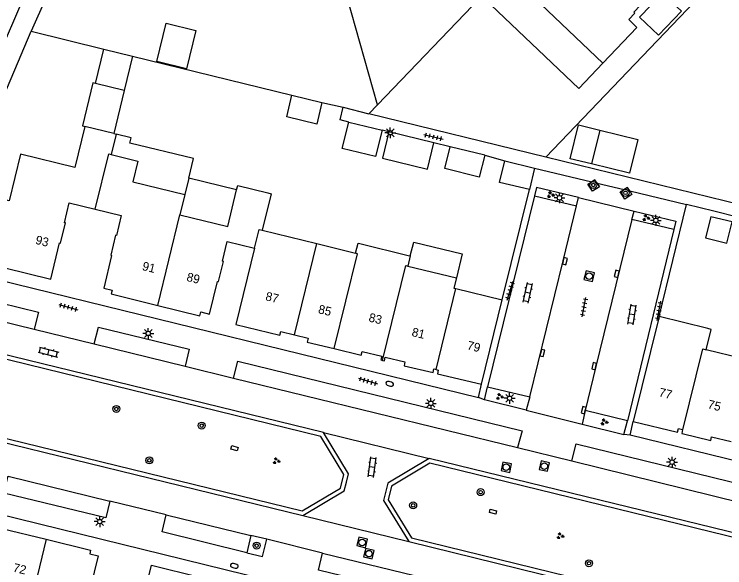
# Model space of a CAD drawing. Extents: x 125000 to 129004, y 397500 to 399008.
# Drawn here: x 126436.9 to 126518.3, y 398005.2 to 398068.5 of the extents above; entities that cross this region are included whole.
import ezdxf

# ---------------------------------------------------------------- set-up
doc = ezdxf.new("R2010")
doc.units = 0
for name, color, linetype in [('gg-afsc-erfafscheiding', 7, 'Continuous'), ('gg-afsc-hekwerk', 7, 'Continuous'), ('gg-anno-huisnummerreeks BGT', 7, 'Continuous'), ('gg-bbg-bijgebouw', 7, 'Continuous'), ('gg-bbg-gedigitaliseerde bijgebouw', 7, 'Continuous'), ('gg-bbg-hoofdgebouw', 7, 'Continuous'), ('gg-bbg-luifel en loopbrug', 7, 'Continuous'), ('gg-bbg-tussenscheiding', 7, 'Continuous'), ('gg-knt-verharding', 7, 'Continuous'), ('gg-knt-verharding nz', 7, 'Continuous'), ('gt-grn-groengrens', 7, 'Continuous'), ('gt-grn-vlakafsluiter', 7, 'Continuous'), ('gt-grn-weggrens', 7, 'Continuous'), ('gt-symb-boom', 7, 'Continuous'), ('gt-symb-brandkraan', 7, 'Continuous'), ('gt-symb-groenvak', 7, 'Continuous'), ('gt-symb-klinker verharding', 7, 'Continuous'), ('gt-symb-kolk', 7, 'Continuous'), ('gt-symb-kolk center center', 7, 'Continuous'), ('gt-symb-lichtmast', 7, 'Continuous'), ('gt-symb-rioolschacht', 7, 'Continuous'), ('gt-symb-tegel verharding', 7, 'Continuous')]:
    doc.layers.add(name, color=color, linetype=linetype)

# ---------------------------------------------------------------- blocks, each defined once
blk = doc.blocks.new('gt0-GRVAK')
at = {"layer": 'gt-symb-groenvak'}
for p, q in [((-0.11, 0.189), (-0.228, 0.24)), ((-0.182, 0.153), (0.088, 0.153)), ((-0.091, 0.211), (-0.156, 0.322)), ((-0.047, 0.214), (-0.047, 0.393)), ((-0.004, 0.211), (0.061, 0.322)), ((0.015, 0.189), (0.133, 0.24)), ((0.262, -0.052), (0.197, 0.059)), ((0.305, -0.049), (0.305, 0.13)), ((0.349, -0.052), (0.414, 0.059)), ((-0.245, -0.228), (-0.363, -0.177)), ((-0.318, -0.264), (-0.047, -0.264)), ((-0.226, -0.206), (-0.291, -0.095)), ((-0.183, -0.203), (-0.183, -0.024)), ((-0.139, -0.206), (-0.074, -0.095)), ((-0.12, -0.228), (-0.002, -0.177)), ((0.243, -0.074), (0.125, -0.023)), ((0.17, -0.11), (0.441, -0.11)), ((0.368, -0.074), (0.486, -0.023))]:
    blk.add_line(p, q, dxfattribs=at)
blk = doc.blocks.new('gt0-BOOM')
at = {"layer": 'gt-symb-boom'}
for radius in [0.4, 0.2]:
    blk.add_circle((0, 0), radius, dxfattribs=at)
blk = doc.blocks.new('gt0-TEG1')
at = {"layer": 'gt-symb-tegel verharding'}
for p, q in [((-1.125, 0), (1.125, 0)), ((-0.9, -0.25), (-0.9, 0.25)), ((-0.45, -0.25), (-0.45, 0.25)), ((0, -0.25), (0, 0.25)), ((0.45, -0.25), (0.45, 0.25)), ((0.9, -0.25), (0.9, 0.25))]:
    blk.add_line(p, q, dxfattribs=at)
blk = doc.blocks.new('gt0-LMAST')
at = {"layer": 'gt-symb-lichtmast'}
for p, q in [((-0.182, 0.173), (-0.447, 0.438)), ((-0.005, 0.246), (-0.005, 0.621)), ((0.172, 0.173), (0.437, 0.438)), ((-0.255, -0.004), (-0.63, -0.004)), ((-0.182, -0.181), (-0.447, -0.446)), ((-0.005, -0.254), (-0.005, -0.629)), ((0.437, -0.446), (0.172, -0.181)), ((0.245, -0.004), (0.62, -0.004))]:
    blk.add_line(p, q, dxfattribs=at)
blk.add_circle((-0.005, -0.004), 0.25, dxfattribs=at)
blk = doc.blocks.new('gt0-KOLK')
at = {"layer": 'gt-symb-kolk'}
blk.add_lwpolyline([(0, 0), (0.375, 0), (0.375, 0.4), (-0.375, 0.4), (-0.375, 0), (0, 0)], dxfattribs=at)
blk = doc.blocks.new('gt0-KL1')
at = {"layer": 'gt-symb-klinker verharding'}
for p, q in [((-1.15, 0.3), (1.15, 0.3)), ((-1, -0.3), (-1, 0.3)), ((-0.5, 0.3), (-0.5, 0.45)), ((0, -0.3), (0, 0.3)), ((0.5, 0.3), (0.5, 0.45)), ((1, -0.3), (1, 0.3)), ((-1.15, -0.3), (1.15, -0.3)), ((-0.5, -0.45), (-0.5, -0.3)), ((0.5, -0.45), (0.5, -0.3))]:
    blk.add_line(p, q, dxfattribs=at)
blk = doc.blocks.new('gt0-RS')
at = {"layer": 'gt-symb-rioolschacht'}
blk.add_lwpolyline([(-0.5, -0.5), (0.5, -0.5), (0.5, 0.5), (-0.5, 0.5)], close=True, dxfattribs=at)
blk.add_circle((0, 0), 0.375, dxfattribs=at)
blk = doc.blocks.new('gt0-KOLKCC')
at = {"layer": 'gt-symb-kolk center center'}
blk.add_lwpolyline([(-0.375, 0.2), (0.375, 0.2), (0.375, -0.2), (-0.375, -0.2)], close=True, dxfattribs=at)
blk = doc.blocks.new('gt0-BR')
at = {"layer": 'gt-symb-brandkraan'}
for centre, radius, start, end in [((-0.244, 0), 0.206, 107.56694, 252.43307), ((0.599, -2.664), 3, 106.89205, 107.56694), ((0, -0.691), 0.938, 73.10799, 106.89205), ((-0.599, -2.664), 3, 72.43309, 73.10799), ((0.244, 0), 0.206, 287.56695, 72.43309), ((0.599, 2.664), 3, 252.43307, 253.10797), ((0, 0.691), 0.938, 253.10797, 286.89206), ((-0.599, 2.664), 3, 286.89206, 287.56695)]:
    blk.add_arc(centre, radius, start, end, dxfattribs=at)

msp = doc.modelspace()

# ---------------------------------------------------------------- linework, layer by layer
at = {"layer": 'gg-afsc-erfafscheiding'}
for p, q in [((126497.759, 398052.161), (126477.496, 398057.12)), ((126479.812, 398055.034), (126479.032, 398055.222)), ((126486.811, 398053.349), (126484.965, 398053.793)), ((126490.772, 398052.372), (126493.061, 398051.732)), ((126517.01, 398045.958), (126513.88, 398046.725)), ((126519.718, 398045.294), (126517.01, 398045.958))]:
    msp.add_line(p, q, dxfattribs=at)
msp.add_lwpolyline([(126475.221, 398056.16), (126474.219, 398056.415), (126474.564, 398057.864)], dxfattribs=at)
at = {"layer": 'gg-afsc-hekwerk'}
for p, q in [((126446.666, 398084.323), (126438.871, 398066.562)), ((126499.871, 398080.447), (126478.524, 398058.123)), ((126478.524, 398058.123), (126474.789, 398071.279)), ((126497.781, 398052.156), (126514.794, 398069.932)), ((126432.376, 398051.273), (126438.871, 398066.562)), ((126477.496, 398057.12), (126478.524, 398058.123)), ((126474.564, 398057.864), (126477.496, 398057.12)), ((126497.781, 398052.156), (126497.759, 398052.161)), ((126558.695, 398037.234), (126497.781, 398052.156)), ((126492.786, 398035.816), (126495.918, 398048.44)), ((126510.759, 398033.93), (126513.88, 398046.725))]:
    msp.add_line(p, q, dxfattribs=at)
at = {"layer": 'gg-bbg-bijgebouw'}
for p, q in [((126446.231, 398060.585), (126447.182, 398064.497)), ((126447.182, 398064.497), (126450.45, 398063.704)), ((126450.45, 398063.704), (126449.506, 398059.794)), ((126449.506, 398059.794), (126446.231, 398060.585)), ((126468.714, 398059.241), (126472.147, 398058.406)), ((126475.221, 398056.16), (126479.032, 398055.222)), ((126490.772, 398052.372), (126486.811, 398053.349)), ((126493.061, 398051.732), (126496.484, 398050.89)), ((126496.484, 398050.89), (126495.918, 398048.44))]:
    msp.add_line(p, q, dxfattribs=at)
for points in [[(126472.147, 398058.406), (126471.568, 398055.943), (126468.122, 398056.753), (126468.714, 398059.241)], [(126479.032, 398055.222), (126478.291, 398052.212), (126474.48, 398053.15), (126475.221, 398056.16)], [(126490.772, 398052.372), (126490.154, 398049.867), (126486.209, 398050.847), (126486.811, 398053.349)], [(126495.918, 398048.44), (126492.469, 398049.238), (126493.061, 398051.732)]]:
    msp.add_lwpolyline(points, dxfattribs=at)
at = {"layer": 'gg-bbg-gedigitaliseerde bijgebouw'}
for p, q in [((126484.965, 398053.793), (126479.812, 398055.034)), ((126503.936, 398055.254), (126502.988, 398051.368))]:
    msp.add_line(p, q, dxfattribs=at)
for points in [[(126457.711, 398066.63), (126456.637, 398062.259), (126453.238, 398063.094), (126454.311, 398067.464), (126457.711, 398066.63)], [(126502.988, 398051.368), (126500.559, 398051.961), (126501.508, 398055.847), (126503.936, 398055.254)], [(126479.812, 398055.034), (126479.076, 398052.02), (126484.225, 398050.763), (126484.965, 398053.793)], [(126518.484, 398042.309), (126519.079, 398044.737), (126516.651, 398045.332), (126516.056, 398042.904), (126518.484, 398042.309)]]:
    msp.add_lwpolyline(points, dxfattribs=at)
at = {"layer": 'gg-bbg-hoofdgebouw'}
for p, q in [((126493.466, 398073.236), (126504.297, 398062.887)), ((126448.324, 398054.841), (126445.011, 398055.657)), ((126448.596, 398054.774), (126448.025, 398052.453)), ((126448.324, 398054.841), (126448.596, 398054.774)), ((126465.303, 398043.801), (126471.549, 398042.257)), ((126471.549, 398042.257), (126476.002, 398041.156)), ((126476.491, 398042.273), (126482.021, 398040.912)), ((126482.26, 398040.853), (126481.973, 398039.688)), ((126482.021, 398040.912), (126482.26, 398040.853)), ((126481.973, 398039.688), (126487.529, 398038.328)), ((126487.466, 398037.109), (126492.786, 398035.816)), ((126490.423, 398026.165), (126492.786, 398035.816)), ((126510.759, 398033.93), (126507.769, 398021.909)), ((126516.298, 398032.549), (126510.759, 398033.93)), ((126521.226, 398028.872), (126516.117, 398030.121))]:
    msp.add_line(p, q, dxfattribs=at)
for points in [[(126504.297, 398062.887), (126508.189, 398067.001), (126507.264, 398067.898), (126507.943, 398068.621), (126507.834, 398068.722), (126512.297, 398073.455), (126507.899, 398077.667), (126506.612, 398076.318), (126504.128, 398078.665), (126501.88, 398076.264), (126501.591, 398076.535), (126499.813, 398074.691), (126497.232, 398077.178), (126493.466, 398073.236)], [(126445.011, 398055.657), (126443.864, 398050.974), (126437.638, 398052.497), (126436.34, 398047.159), (126435.32, 398047.408), (126434.335, 398043.384), (126435.343, 398043.136), (126434.641, 398040.221), (126435.975, 398039.898), (126435.871, 398039.471), (126441.108, 398038.201), (126442.119, 398042.343), (126442.226, 398042.317), (126442.791, 398044.63), (126442.684, 398044.656), (126443.235, 398046.911), (126446.211, 398046.185)], [(126448.025, 398052.453), (126451.094, 398051.681), (126450.506, 398049.344), (126456.443, 398047.895)], [(126455.899, 398045.553), (126461.362, 398044.219), (126462.386, 398048.415)], [(126462.386, 398048.415), (126462.505, 398048.901), (126465.962, 398048.057)], [(126456.443, 398047.895), (126455.873, 398045.559), (126455.899, 398045.553)], [(126465.962, 398048.057), (126466.33, 398047.967), (126465.303, 398043.801)], [(126446.211, 398046.185), (126449.187, 398045.458), (126448.636, 398043.203), (126448.53, 398043.229), (126447.969, 398040.922), (126448.076, 398040.896), (126447.167, 398037.17), (126448.137, 398036.927), (126448.032, 398036.5), (126453.369, 398035.188)], [(126453.369, 398035.188), (126458.183, 398034.01), (126458.288, 398034.438), (126459.259, 398034.2), (126460.195, 398037.937), (126460.302, 398037.91), (126460.87, 398040.232), (126460.763, 398040.258), (126461.314, 398042.512), (126464.423, 398041.751)], [(126476.002, 398041.156), (126476.29, 398042.323), (126476.491, 398042.273)], [(126464.423, 398041.751), (126462.284, 398033.009), (126467.328, 398031.775), (126467.432, 398032.203), (126469.001, 398031.817)], [(126487.529, 398038.328), (126487.244, 398037.163), (126487.466, 398037.109)], [(126516.117, 398030.121), (126516.698, 398032.449), (126516.298, 398032.549)], [(126469.001, 398031.817), (126470.569, 398031.431), (126470.465, 398031.004), (126473.556, 398030.251)], [(126473.556, 398030.251), (126476.647, 398029.497), (126476.755, 398029.937), (126478.994, 398029.385), (126478.888, 398028.955), (126479.089, 398028.904)], [(126479.089, 398028.904), (126479.29, 398028.852), (126479.399, 398029.278), (126481.651, 398028.725), (126481.547, 398028.297), (126484.858, 398027.498), (126484.96, 398027.919), (126485.208, 398027.86)], [(126485.208, 398027.86), (126485.456, 398027.801), (126485.354, 398027.373), (126490.423, 398026.165)], [(126507.769, 398021.909), (126512.833, 398020.673), (126512.938, 398021.1), (126513.423, 398020.982)], [(126513.423, 398020.982), (126513.326, 398020.553), (126513.356, 398020.546)], [(126513.356, 398020.546), (126516.638, 398019.737), (126516.744, 398020.164), (126518.981, 398019.614)], [(126429.466, 398001.931), (126432.435, 398001.214), (126432.98, 398003.468), (126432.873, 398003.493), (126433.43, 398005.796), (126433.536, 398005.77), (126434.434, 398009.484), (126435.413, 398009.248), (126435.517, 398009.675), (126440.596, 398008.435)], [(126440.596, 398008.435), (126445.675, 398007.194), (126445.57, 398006.766), (126446.544, 398006.527), (126445.629, 398002.789), (126445.736, 398002.763), (126445.166, 398000.437), (126445.059, 398000.463), (126444.506, 397998.204), (126447.495, 397997.472)], [(126447.495, 397997.472), (126450.483, 397996.741), (126451.036, 397999), (126450.929, 397999.026), (126451.496, 398001.343), (126451.603, 398001.317), (126452.623, 398005.483), (126458.183, 398004.12)]]:
    msp.add_lwpolyline(points, dxfattribs=at)
at = {"layer": 'gg-bbg-luifel en loopbrug'}
for p, q in [((126449.506, 398059.794), (126448.324, 398054.841)), ((126456.897, 398049.755), (126456.443, 398047.895)), ((126462.386, 398048.415), (126456.897, 398049.755))]:
    msp.add_line(p, q, dxfattribs=at)
for points in [[(126493.466, 398073.236), (126490.703, 398070.344), (126501.534, 398059.995), (126504.297, 398062.887)], [(126508.5, 398068.165), (126511.125, 398070.912), (126513.294, 398068.84), (126510.669, 398066.092), (126508.5, 398068.165)], [(126446.231, 398060.585), (126445.94, 398060.657), (126444.726, 398055.727), (126445.011, 398055.657)], [(126456.897, 398049.755), (126457.443, 398051.99), (126450.157, 398053.768), (126450.301, 398054.358), (126448.596, 398054.774)], [(126503.936, 398055.254), (126508.308, 398054.187), (126507.36, 398050.302), (126502.988, 398051.368)], [(126482.26, 398040.853), (126482.651, 398042.441), (126488.205, 398041.074), (126487.529, 398038.328)]]:
    msp.add_lwpolyline(points, dxfattribs=at)
at = {"layer": 'gg-bbg-tussenscheiding'}
for p, q in [((126453.369, 398035.188), (126455.899, 398045.553)), ((126469.001, 398031.817), (126471.549, 398042.257)), ((126485.208, 398027.86), (126487.466, 398037.109))]:
    msp.add_line(p, q, dxfattribs=at)
for points in [[(126446.211, 398046.185), (126447.757, 398052.52), (126448.025, 398052.453)], [(126464.423, 398041.751), (126464.945, 398043.89), (126465.303, 398043.801)], [(126473.556, 398030.251), (126476.206, 398041.106), (126476.002, 398041.156)], [(126479.089, 398028.904), (126481.736, 398039.746), (126481.973, 398039.688)], [(126513.423, 398020.982), (126513.461, 398020.973), (126515.726, 398030.217), (126516.117, 398030.121)], [(126440.596, 398008.435), (126437.808, 397996.896), (126438.016, 397996.845)]]:
    msp.add_lwpolyline(points, dxfattribs=at)
at = {"layer": 'gg-knt-verharding'}
for p, q in [((126496.459, 398047.735), (126491.103, 398025.877)), ((126496.459, 398047.735), (126501.279, 398046.577)), ((126501.279, 398046.577), (126501.501, 398047.536)), ((126507.615, 398045.03), (126507.861, 398045.984)), ((126512.419, 398043.862), (126507.615, 398045.03)), ((126512.419, 398043.862), (126507.098, 398021.996)), ((126427.531, 398039.968), (126490.06, 398024.642)), ((126472.323, 398020.648), (126421.117, 398033.16)), ((126439.2, 398032.462), (126446.064, 398030.791)), ((126456.479, 398028.241), (126462.023, 398026.864)), ((126490.06, 398024.642), (126490.423, 398026.165)), ((126490.765, 398024.379), (126491.103, 398025.877)), ((126491.103, 398025.877), (126495.932, 398024.715)), ((126495.932, 398024.715), (126495.521, 398023.199)), ((126495.521, 398023.199), (126490.765, 398024.379)), ((126418.425, 398023.739), (126469.973, 398011.151)), ((126502.289, 398023.161), (126501.93, 398021.611)), ((126507.098, 398021.996), (126502.289, 398023.161)), ((126501.93, 398021.611), (126506.714, 398020.433)), ((126506.714, 398020.433), (126507.098, 398021.996)), ((126507.432, 398020.343), (126507.769, 398021.909)), ((126474.648, 398015.856), (126472.003, 398020.211)), ((126684.578, 397977.097), (126507.432, 398020.343)), ((126494.535, 398018.934), (126500.727, 398017.394)), ((126680.269, 397969.791), (126484.428, 398017.669)), ((126682.484, 397968.735), (126484.508, 398017.135)), ((126417.28, 398015.702), (126579.422, 397976.046)), ((126454.327, 398011.228), (126447.887, 398012.785)), ((126464.007, 398008.877), (126463.533, 398006.895)), ((126465.828, 398008.433), (126464.007, 398008.877)), ((126472.224, 398006.846), (126465.828, 398008.433)), ((126482.394, 398008.606), (126680.419, 397960.251)), ((126482.075, 398008.169), (126677.934, 397960.343))]:
    msp.add_line(p, q, dxfattribs=at)
for points in [[(126503.64, 398049.177), (126503.927, 398048.739), (126503.121, 398048.246), (126502.586, 398049.062), (126503.017, 398049.326)], [(126503.64, 398049.177), (126503.392, 398049.555), (126503.017, 398049.326)], [(126501.501, 398047.536), (126496.699, 398048.671), (126496.459, 398047.735)], [(126507.365, 398048.285), (126507.63, 398047.866), (126506.803, 398047.36), (126506.29, 398048.171), (126506.725, 398048.438)], [(126507.365, 398048.285), (126507.117, 398048.678), (126506.725, 398048.438)], [(126495.932, 398024.715), (126499.756, 398040.293), (126501.279, 398046.577)], [(126507.861, 398045.984), (126512.666, 398044.818), (126512.419, 398043.862)], [(126507.615, 398045.03), (126503.494, 398028.192), (126502.289, 398023.161)], [(126426.623, 398037.628), (126439.718, 398034.413), (126439.2, 398032.462)], [(126472.003, 398020.211), (126420.621, 398032.767), (126420.736, 398033.238)], [(126446.064, 398030.791), (126446.565, 398032.719), (126456.941, 398030.187), (126456.479, 398028.241)], [(126462.023, 398026.864), (126462.518, 398028.826), (126495.052, 398020.853), (126494.535, 398018.934)], [(126418.425, 398023.739), (126418.544, 398024.225), (126469.892, 398011.685)], [(126474.939, 398014.955), (126475.183, 398015.937), (126472.323, 398020.648)], [(126500.727, 398017.394), (126501.227, 398019.359), (126555.856, 398005.956), (126555.377, 398004)], [(126484.428, 398017.669), (126479.676, 398014.842), (126479.205, 398012.858), (126482.075, 398008.169)], [(126484.508, 398017.135), (126480.114, 398014.521), (126479.739, 398012.943), (126482.394, 398008.606)], [(126469.892, 398011.685), (126474.26, 398014.295), (126474.648, 398015.856)], [(126447.887, 398012.785), (126447.42, 398010.899), (126435.726, 398013.704), (126436.225, 398015.67)], [(126469.973, 398011.151), (126474.695, 398013.973), (126474.939, 398014.955)], [(126463.533, 398006.895), (126453.846, 398009.275), (126454.327, 398011.228)], [(126463.533, 398006.895), (126465.339, 398006.457), (126465.828, 398008.433)], [(126484.004, 398003.971), (126483.533, 398002.031), (126471.736, 398004.912), (126472.224, 398006.846)]]:
    msp.add_lwpolyline(points, dxfattribs=at)
at = {"layer": 'gg-knt-verharding nz'}
for p, q in [((126426.123, 398035.643), (126439.2, 398032.462)), ((126446.064, 398030.791), (126456.479, 398028.241)), ((126462.023, 398026.864), (126494.535, 398018.934)), ((126500.727, 398017.394), (126555.377, 398004)), ((126436.225, 398015.67), (126447.887, 398012.785)), ((126454.327, 398011.228), (126464.007, 398008.877)), ((126472.224, 398006.846), (126484.004, 398003.971))]:
    msp.add_line(p, q, dxfattribs=at)
at = {"layer": 'gt-grn-groengrens'}
msp.add_line((126425.544, 398041.334), (126447.287, 398092.068), dxfattribs=at)
at = {"layer": 'gt-grn-vlakafsluiter'}
for p, q in [((126438.871, 398066.562), (126447.182, 398064.497)), ((126450.45, 398063.704), (126468.714, 398059.241)), ((126472.147, 398058.406), (126474.564, 398057.864))]:
    msp.add_line(p, q, dxfattribs=at)
at = {"layer": 'gt-grn-weggrens'}
for p, q in [((126496.484, 398050.89), (126503.017, 398049.326)), ((126503.64, 398049.177), (126506.725, 398048.438)), ((126507.365, 398048.285), (126513.88, 398046.725)), ((126501.501, 398047.536), (126507.861, 398045.984)), ((126490.765, 398024.379), (126490.06, 398024.642)), ((126495.521, 398023.199), (126501.93, 398021.611)), ((126472.323, 398020.648), (126484.428, 398017.669)), ((126507.432, 398020.343), (126506.714, 398020.433)), ((126469.973, 398011.151), (126482.075, 398008.169))]:
    msp.add_line(p, q, dxfattribs=at)

# ---------------------------------------------------------------- block references
at = {"layer": 'gt-symb-boom'}
for p in [(126503.207, 398048.973), (126506.893, 398048.068), (126448.624, 398023.344), (126458.392, 398021.442), (126452.398, 398017.466), (126490.307, 398013.831), (126482.585, 398012.329), (126464.666, 398007.716), (126502.702, 398005.696)]:
    msp.add_blockref('gt0-BOOM', p, dxfattribs=at)
at = {"layer": 'gt-symb-brandkraan'}
for p, rotation in [((126479.909, 398026.214), -14.717311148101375), ((126462.117, 398005.406), 166.88085536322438)]:
    msp.add_blockref('gt0-BR', p, dxfattribs=dict(at, rotation=rotation))
at = {"layer": 'gt-symb-groenvak'}
for p in [(126498.307, 398047.852), (126509.232, 398045.209), (126492.486, 398024.762), (126504.441, 398021.85), (126466.926, 398017.407), (126499.411, 398008.819)]:
    msp.add_blockref('gt0-GRVAK', p, dxfattribs=at)
at = {"layer": 'gt-symb-klinker verharding'}
for p, rotation in [((126495.71, 398036.634), 77.52092819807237), ((126507.638, 398034.143), 80.67893928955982), ((126440.85, 398029.843), -14.119602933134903), ((126477.899, 398016.68), 82.1858191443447)]:
    msp.add_blockref('gt0-KL1', p, dxfattribs=dict(at, rotation=rotation))
at = {"layer": 'gt-symb-kolk'}
for p, rotation in [((126499.756, 398040.293), -103.77214543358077), ((126506.081, 398038.751), 76.28353067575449), ((126497.184, 398029.793), -103.8277950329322), ((126503.494, 398028.192), 76.22785456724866), ((126502.289, 398023.161), 76.51987378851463)]:
    msp.add_blockref('gt0-KOLK', p, dxfattribs=dict(at, rotation=rotation))
at = {"layer": 'gt-symb-kolk center center'}
for p, rotation in [((126462.151, 398018.855), 164.3378936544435), ((126491.718, 398011.59), 165.64421500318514)]:
    msp.add_blockref('gt0-KOLKCC', p, dxfattribs=dict(at, rotation=rotation))
at = {"layer": 'gt-symb-lichtmast'}
for p in [(126479.968, 398054.939), (126499.34, 398047.5), (126510.365, 398044.914), (126452.272, 398031.984), (126493.629, 398024.572), (126484.613, 398023.992), (126512.228, 398017.262), (126446.716, 398010.464)]:
    msp.add_blockref('gt0-LMAST', p, dxfattribs=at)
at = {"layer": 'gt-symb-rioolschacht'}
for p, rotation in [((126502.74, 398038.536), -104.06403671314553), ((126497.599, 398016.812), 167.35314650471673), ((126493.246, 398016.682), 168.1732960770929), ((126476.75, 398008.073), 166.06098564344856), ((126477.526, 398006.792), 166.29711003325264)]:
    msp.add_blockref('gt0-RS', p, dxfattribs=dict(at, rotation=rotation))
at = {"layer": 'gt-symb-tegel verharding'}
for p, rotation in [((126484.913, 398054.475), -14.11960293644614), ((126493.696, 398036.882), 72.77930062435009), ((126502.14, 398034.978), 78.81367070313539), ((126443.125, 398034.992), -15.787947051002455), ((126510.72, 398034.568), 79.04956573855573), ((126477.414, 398026.534), -17.22069937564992)]:
    msp.add_blockref('gt0-TEG1', p, dxfattribs=dict(at, rotation=rotation))

# ---------------------------------------------------------------- texts
at = {"layer": 'gg-anno-huisnummerreeks BGT'}
for s, rotation, p in [('93', 346.4, (126439.296, 398042.242)), ('91', 346.2, (126451.51, 398039.248)), ('89', 346.2, (126456.585, 398038.004)), ('87', 346.2, (126465.615, 398035.797)), ('85', 346.3, (126471.652, 398034.317)), ('83', 346.2, (126477.428, 398033.374)), ('81', 346.4, (126482.354, 398031.704)), ('79', 346.6, (126488.691, 398030.176)), ('77', 346.3, (126510.638, 398024.811)), ('75', 346.2, (126516.227, 398023.441)), ('72', 346.3, (126436.719, 398004.749))]:
    msp.add_text(s, height=1, rotation=rotation, dxfattribs=at).set_placement(p)

doc.saveas('drawing.dxf')
